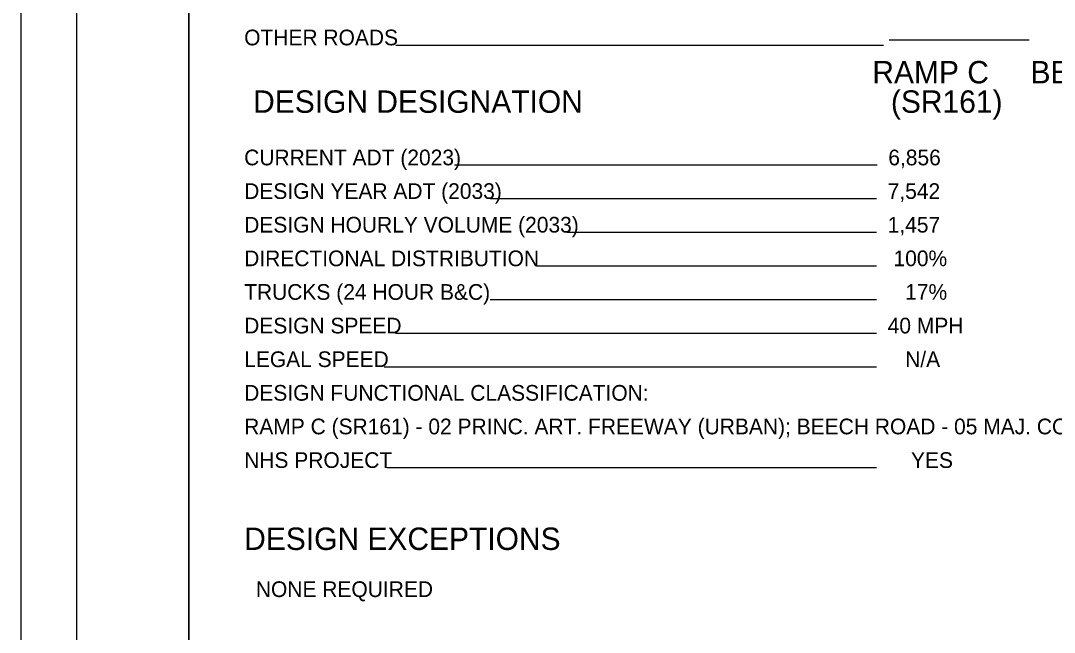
# Model space of a CAD drawing. Extents: x 0 to 91.3, y -0.7 to 22.
# Drawn here: x 0 to 9.22, y 5.64 to 11.1 of the extents above; entities that cross this region are included whole.
import ezdxf

# ---------------------------------------------------------------- set-up
doc = ezdxf.new("R2010")
doc.units = 0
for name, color, linetype in [('SH_Border', 7, 'Continuous'), ('SH_Cut_Line', 7, 'Continuous'), ('SH_Data', 7, 'Continuous'), ('SH_Text', 7, 'Continuous')]:
    doc.layers.add(name, color=color, linetype=linetype)

msp = doc.modelspace()

# ---------------------------------------------------------------- linework, layer by layer
at = {"layer": 'SH_Border'}
for points in [[(0.5, 21.5), (1.5, 21.5), (1.5, 0.5), (0.5, 0.5)], [(1.5, 21.5), (33.5, 21.5), (33.5, 0.5), (1.5, 0.5)]]:
    msp.add_lwpolyline(points, close=True, dxfattribs=at)
at = {"layer": 'SH_Cut_Line'}
msp.add_lwpolyline([(0, 0), (34, 0), (34, 22), (0, 22)], close=True, dxfattribs=at)
at = {"layer": 'SH_Data'}
for p, q in [((9, 10.9223), (7.75, 10.9223)), ((7.7, 10.8767), (3.3471, 10.8767)), ((7.6424, 9.8062), (3.871, 9.8062)), ((7.6368, 9.5062), (4.1885, 9.5062)), ((7.6368, 9.2062), (4.8723, 9.2062)), ((7.6368, 8.9062), (4.6037, 8.9062)), ((7.6368, 8.6062), (4.1885, 8.6062)), ((7.6368, 8.3062), (3.346, 8.3062)), ((7.6368, 8.0062), (3.2422, 8.0062)), ((7.6368, 7.1062), (3.2669, 7.1062))]:
    msp.add_line(p, q, dxfattribs=at)

# ---------------------------------------------------------------- texts
for s, p in [('RAMP C     BEECH ROAD', (7.6, 10.5372)), (' DESIGN DESIGNATION                                     (SR161)          (TR88)', (2, 10.2747))]:
    msp.add_text(s, height=0.2, dxfattribs=at).set_placement(p)
at = {"layer": 'SH_Text'}
for s, height, p in [('OTHER ROADS', 0.14, (1.9944, 10.8767)), ('CURRENT ADT (2023)', 0.14, (1.9944, 9.8062)), ('6,856', 0.14, (7.7424, 9.8062)), ('DESIGN YEAR ADT (2033)', 0.14, (1.9944, 9.5062)), ('7,542', 0.14, (7.7368, 9.5062)), ('DESIGN HOURLY VOLUME (2033)', 0.14, (1.9944, 9.2062)), ('1,457', 0.14, (7.7368, 9.2062)), ('DIRECTIONAL DISTRIBUTION', 0.14, (1.9944, 8.9062)), (' 100%', 0.14, (7.7368, 8.9062)), ('TRUCKS (24 HOUR B&C)', 0.14, (1.9944, 8.6062)), ('   17%', 0.14, (7.7368, 8.6062)), ('DESIGN SPEED', 0.14, (1.9944, 8.3062)), ('40 MPH ', 0.14, (7.7368, 8.3062)), ('LEGAL SPEED', 0.14, (1.9944, 8.0062)), ('   N/A', 0.14, (7.7368, 8.0062)), ('DESIGN FUNCTIONAL CLASSIFICATION:', 0.14, (1.9944, 7.7062)), ('RAMP C (SR161) - 02 PRINC. ART. FREEWAY (URBAN); BEECH ROAD - 05 MAJ. COLLECTOR (URBAN)                  ', 0.14, (1.9944, 7.4062)), ('NHS PROJECT', 0.14, (1.9944, 7.1062)), ('    YES', 0.14, (7.7368, 7.1062)), ('DESIGN EXCEPTIONS', 0.2, (1.9944, 6.3744)), ('  NONE REQUIRED', 0.14, (1.9944, 5.9544))]:
    msp.add_text(s, height=height, dxfattribs=at).set_placement(p)

doc.saveas('drawing.dxf')
